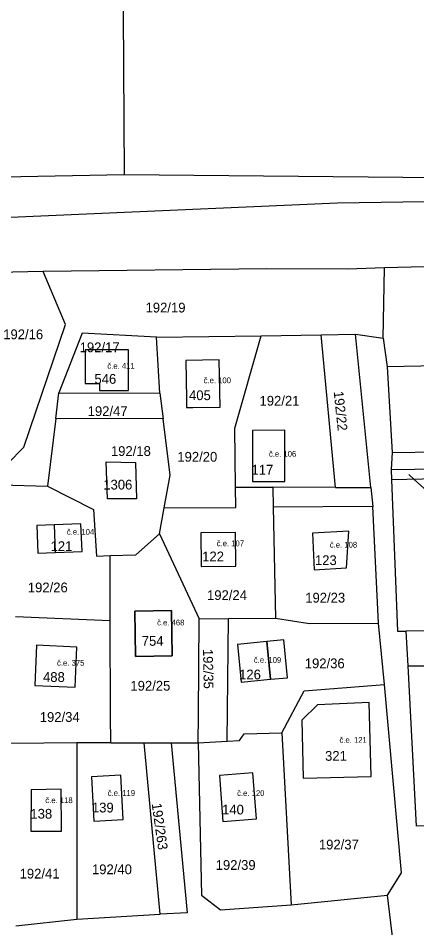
# Model space of a CAD drawing. Extents: x -887272 to -877616, y -1026687 to -1019819.
# Drawn here: x -882463.7 to -882394.3, y -1024170.3 to -1024011.9 of the extents above; entities that cross this region are included whole.
import ezdxf

# ---------------------------------------------------------------- set-up
doc = ezdxf.new("R2010")
doc.units = 0
for name, color, linetype in [('Definiční body', 7, 'Continuous'), ('Hranice parcel', 7, 'Continuous'), ('Parcelní čísla', 7, 'Continuous'), ('Polygon budovy', 7, 'Continuous'), ('Pop  PČ popisy', 7, 'Continuous'), ('Vnitřní kresba', 7, 'Continuous')]:
    doc.layers.add(name, color=color, linetype=linetype)

msp = doc.modelspace()

# ---------------------------------------------------------------- linework, layer by layer
at = {"layer": 'Hranice parcel'}
for p, q in [((-882384.42, -1024039.73), (-882445.26, -1024039.2)), ((-882376.66, -1024054.74), (-882399.93, -1024055.4)), ((-882459.39, -1024055.99), (-882468.38, -1024056.21)), ((-882400.17, -1024067.6), (-882399.93, -1024055.4)), ((-882439.63, -1024067.48), (-882421.39, -1024067.22)), ((-882439.03, -1024077.2), (-882439.63, -1024067.48)), ((-882421.39, -1024067.22), (-882410.99, -1024067.03)), ((-882410.99, -1024067.03), (-882404.99, -1024066.92)), ((-882408.49, -1024093.61), (-882410.99, -1024067.03)), ((-882404.99, -1024066.92), (-882400.17, -1024067.6)), ((-882400.17, -1024067.6), (-882399.46, -1024072.61)), ((-882378.73, -1024072.28), (-882399.46, -1024072.61)), ((-882399.46, -1024072.61), (-882398.59, -1024087.52)), ((-882457.19, -1024081.63), (-882456.65, -1024077.16)), ((-882456.65, -1024077.16), (-882439.03, -1024077.2)), ((-882439.03, -1024077.2), (-882438.47, -1024081.67)), ((-882457.19, -1024081.63), (-882458.6, -1024093.38)), ((-882438.47, -1024081.67), (-882457.19, -1024081.63)), ((-882398.59, -1024087.52), (-882398.79, -1024090.5)), ((-882398.59, -1024087.52), (-882377.91, -1024087.31)), ((-882398.79, -1024090.5), (-882382.57, -1024090.25)), ((-882398.79, -1024090.5), (-882398.72, -1024092.28)), ((-882466.65, -1024093.19), (-882458.6, -1024093.38)), ((-882382.62, -1024092.03), (-882398.72, -1024092.28)), ((-882425.89, -1024093.57), (-882419.37, -1024093.58)), ((-882419.37, -1024093.58), (-882419.3, -1024097.06)), ((-882408.49, -1024093.61), (-882419.37, -1024093.58)), ((-882439.12, -1024101.73), (-882438.28, -1024097.17)), ((-882419.3, -1024097.06), (-882418.9, -1024116.42)), ((-882439.12, -1024101.73), (-882432.22, -1024116.49)), ((-882447.68, -1024116.83), (-882447.72, -1024105.51)), ((-882464.18, -1024116.13), (-882447.68, -1024116.83)), ((-882432.22, -1024116.49), (-882427.09, -1024116.46)), ((-882427.35, -1024137.82), (-882427.09, -1024116.46)), ((-882427.09, -1024116.46), (-882418.9, -1024116.42)), ((-882399.92, -1024127.96), (-882400.99, -1024117.27)), ((-882383.34, -1024118.62), (-882396.14, -1024118.64)), ((-882395.82, -1024124.73), (-882396.14, -1024118.64)), ((-882395.82, -1024124.73), (-882386.09, -1024124.66)), ((-882394.36, -1024152.64), (-882395.82, -1024124.73)), ((-882417.8, -1024136.36), (-882416.18, -1024166.34)), ((-882453.49, -1024138.14), (-882465, -1024138.24)), ((-882453.49, -1024138.14), (-882453.52, -1024168.83)), ((-882447.61, -1024138.14), (-882453.49, -1024138.14)), ((-882447.61, -1024138.14), (-882441.77, -1024138.13)), ((-882438.97, -1024167.97), (-882441.77, -1024138.13)), ((-882441.77, -1024138.13), (-882437.06, -1024138.13)), ((-882437.06, -1024138.13), (-882432.39, -1024138.13)), ((-882432.39, -1024138.13), (-882427.35, -1024137.82)), ((-882385.89, -1024152.42), (-882394.36, -1024152.64)), ((-882416.18, -1024166.34), (-882399.41, -1024164.66)), ((-882398.41, -1024172.81), (-882399.41, -1024164.66)), ((-882464.13, -1024169.99), (-882453.52, -1024168.83)), ((-882453.52, -1024168.83), (-882438.97, -1024167.97))]:
    msp.add_line(p, q, dxfattribs=at)
for points in [[(-882571.48, -1023926.26), (-882445.96, -1023926.09), (-882445.26, -1024039.2)], [(-882445.26, -1024039.2), (-882496.32, -1024040.18), (-882559.82, -1024040.7), (-882602.37, -1024040.09)], [(-882603.02, -1024045.76), (-882539.56, -1024043.76), (-882473.06, -1024046.88), (-882408.1, -1024044.08), (-882339.94, -1024043.02), (-882340.1, -1024040.68)], [(-882465.58, -1024089.52), (-882462.72, -1024086.61), (-882455.48, -1024065.24), (-882459.39, -1024055.99)], [(-882399.93, -1024055.4), (-882406.36, -1024055.62), (-882420.44, -1024055.54), (-882459.39, -1024055.99)], [(-882439.63, -1024067.48), (-882452.56, -1024066.78), (-882456.65, -1024077.16)], [(-882425.89, -1024093.57), (-882425.98, -1024083.3), (-882421.39, -1024067.22)], [(-882408.49, -1024093.61), (-882402.31, -1024093.63), (-882404.99, -1024066.92)], [(-882452.04, -1024069.67), (-882452.03, -1024075.52), (-882449.56, -1024075.52), (-882449.56, -1024076.75), (-882444.53, -1024076.75), (-882444.5, -1024069.65), (-882452.04, -1024069.67)], [(-882434.39, -1024079.72), (-882433.31, -1024079.71), (-882428.57, -1024079.63), (-882428.71, -1024071.42), (-882434.53, -1024071.52), (-882434.42, -1024078.2), (-882434.39, -1024079.72)], [(-882438.28, -1024097.17), (-882437.23, -1024091.5), (-882438.47, -1024081.67)], [(-882417.29, -1024083.68), (-882422.93, -1024083.73), (-882422.91, -1024092.62), (-882417.28, -1024092.58), (-882417.29, -1024083.68)], [(-882448.14, -1024095.6), (-882448.38, -1024089.18), (-882443.3, -1024089.26), (-882443.1, -1024095.6), (-882448.14, -1024095.6)], [(-882398.72, -1024092.28), (-882397.69, -1024118.64), (-882396.14, -1024118.64)], [(-882458.6, -1024093.38), (-882450.61, -1024097.46), (-882450.06, -1024105.58), (-882447.72, -1024105.51)], [(-882438.28, -1024097.17), (-882425.81, -1024097.1), (-882425.89, -1024093.57)], [(-882400.99, -1024117.27), (-882401.99, -1024096.95), (-882419.3, -1024097.06)], [(-882457.28, -1024104.98), (-882452.6, -1024104.8), (-882452.78, -1024099.98), (-882457.45, -1024100.16), (-882460.45, -1024100.28), (-882460.28, -1024105.1), (-882457.28, -1024104.98)], [(-882412.16, -1024108), (-882406.54, -1024107.62), (-882406.16, -1024101.24), (-882412.46, -1024101.62), (-882412.16, -1024108)], [(-882447.72, -1024105.51), (-882443.26, -1024105.38), (-882439.12, -1024101.73)], [(-882425.8, -1024107.33), (-882425.86, -1024101.46), (-882431.91, -1024101.53), (-882431.83, -1024107.39), (-882425.8, -1024107.33)], [(-882436.89, -1024122.96), (-882443.29, -1024123.08), (-882443.39, -1024115.2), (-882437.02, -1024115.09), (-882436.89, -1024122.96)], [(-882447.61, -1024138.14), (-882447.63, -1024133.32), (-882447.68, -1024116.83)], [(-882432.39, -1024138.13), (-882432.35, -1024133.31), (-882432.22, -1024116.49)], [(-882418.9, -1024116.42), (-882412.99, -1024117.3), (-882400.99, -1024117.27)], [(-882425.54, -1024120.96), (-882424.92, -1024127.53), (-882419.79, -1024127.05), (-882416.85, -1024126.78), (-882417.47, -1024120.19), (-882420.41, -1024120.47), (-882425.54, -1024120.96)], [(-882453.8, -1024128.42), (-882453.49, -1024121.43), (-882460.5, -1024121.09), (-882460.79, -1024128.11), (-882453.8, -1024128.42)], [(-882417.8, -1024136.36), (-882413.94, -1024129.03), (-882399.92, -1024127.96)], [(-882399.41, -1024164.66), (-882396.97, -1024160.77), (-882399.92, -1024127.96)], [(-882411.59, -1024131.48), (-882414.33, -1024134.16), (-882414.12, -1024144.27), (-882402.27, -1024143.98), (-882402.59, -1024131.11), (-882411.59, -1024131.48)], [(-882427.35, -1024137.82), (-882425.17, -1024137.68), (-882424.39, -1024136.54), (-882417.8, -1024136.36)], [(-882437.06, -1024138.13), (-882434.29, -1024167.7), (-882438.97, -1024167.97)], [(-882432.39, -1024138.13), (-882431.82, -1024164.63), (-882428.47, -1024167.2), (-882416.18, -1024166.34)], [(-882445.82, -1024143.75), (-882450.96, -1024144.04), (-882450.53, -1024151.78), (-882445.44, -1024151.49), (-882445.82, -1024143.75)], [(-882422.22, -1024151.37), (-882422.84, -1024143.36), (-882428.67, -1024143.82), (-882428.08, -1024151.8), (-882422.22, -1024151.37)], [(-882456.24, -1024146.16), (-882461.48, -1024146.3), (-882461.51, -1024153.52), (-882456.18, -1024153.5), (-882456.24, -1024146.16)]]:
    msp.add_lwpolyline(points, dxfattribs=at)
at = {"layer": 'Polygon budovy'}
for points in [[(-882444.53, -1024076.75), (-882444.5, -1024069.65), (-882452.04, -1024069.67), (-882452.03, -1024075.52), (-882449.56, -1024075.52), (-882449.56, -1024076.75)], [(-882434.53, -1024071.52), (-882434.42, -1024078.2), (-882434.39, -1024079.72), (-882433.31, -1024079.71), (-882428.57, -1024079.63), (-882428.71, -1024071.42)], [(-882422.93, -1024083.73), (-882422.91, -1024092.62), (-882417.28, -1024092.58), (-882417.29, -1024083.68)], [(-882457.45, -1024100.16), (-882457.28, -1024104.98), (-882452.6, -1024104.8), (-882452.78, -1024099.98)], [(-882412.46, -1024101.62), (-882412.16, -1024108), (-882406.54, -1024107.62), (-882406.16, -1024101.24)], [(-882425.86, -1024101.46), (-882431.91, -1024101.53), (-882431.83, -1024107.39), (-882425.8, -1024107.33)], [(-882443.39, -1024115.2), (-882443.29, -1024123.08), (-882436.89, -1024122.96), (-882437.02, -1024115.09)], [(-882460.79, -1024128.11), (-882453.8, -1024128.42), (-882453.49, -1024121.43), (-882460.5, -1024121.09)], [(-882424.92, -1024127.53), (-882419.79, -1024127.05), (-882420.41, -1024120.47), (-882425.54, -1024120.96)], [(-882411.59, -1024131.48), (-882414.33, -1024134.16), (-882414.12, -1024144.27), (-882402.27, -1024143.98), (-882402.59, -1024131.11)], [(-882450.53, -1024151.78), (-882445.44, -1024151.49), (-882445.82, -1024143.75), (-882450.96, -1024144.04)], [(-882428.08, -1024151.8), (-882422.22, -1024151.37), (-882422.84, -1024143.36), (-882428.67, -1024143.82)], [(-882461.48, -1024146.3), (-882461.51, -1024153.52), (-882456.18, -1024153.5), (-882456.24, -1024146.16)]]:
    msp.add_lwpolyline(points, close=True, dxfattribs=at)
at = {"layer": 'Pop  PČ popisy'}
for p, q in [((-882395.72, -1024091.38), (-882394.75, -1024092.24)), ((-882394.75, -1024092.24), (-882392.52, -1024094.25))]:
    msp.add_line(p, q, dxfattribs=at)
at = {"layer": 'Vnitřní kresba'}
for p, q in [((-882402.31, -1024093.63), (-882401.99, -1024096.95)), ((-882457.45, -1024100.16), (-882457.28, -1024104.98)), ((-882420.41, -1024120.47), (-882419.79, -1024127.05))]:
    msp.add_line(p, q, dxfattribs=at)

# ---------------------------------------------------------------- texts
at = {"layer": 'Definiční body'}
for s, p in [('č.e. 411', (-882448.19, -1024072.95)), ('č.e. 100', (-882431.43, -1024075.47)), ('č.e. 106', (-882420.06, -1024088.28)), ('č.e. 104', (-882455.24, -1024101.87)), ('č.e. 107', (-882429.15, -1024103.87)), ('č.e. 108', (-882409.46, -1024104.11)), ('č.e. 468', (-882439.53, -1024117.66)), ('č.e. 109', (-882422.68, -1024124.18)), ('č.e. 375', (-882456.95, -1024124.68)), ('č.e. 121', (-882407.78, -1024138.11)), ('č.e. 119', (-882448.12, -1024147.35)), ('č.e. 120', (-882425.6, -1024147.37)), ('č.e. 118', (-882458.99, -1024148.61))]:
    msp.add_text(s, height=1, dxfattribs=at).set_placement(p)
at = {"layer": 'Parcelní čísla'}
for s, p in [('192/19', (-882441.54, -1024063.15)), ('192/16', (-882466.32, -1024067.81)), ('192/17', (-882453.01, -1024070.07)), ('546', (-882450.44, -1024075.58)), ('405', (-882433.97, -1024078.42)), ('192/21', (-882421.7, -1024079.38)), ('192/47', (-882451.62, -1024081.19)), ('192/18', (-882447.57, -1024088.14)), ('192/20', (-882436.01, -1024089.14)), ('117', (-882423.09, -1024091.39)), ('1306', (-882448.9, -1024093.99)), ('121', (-882458.08, -1024104.71)), ('122', (-882431.68, -1024106.5)), ('123', (-882412.05, -1024107.15)), ('192/26', (-882462.04, -1024111.9)), ('192/24', (-882430.84, -1024113.24)), ('192/23', (-882413.74, -1024113.68)), ('754', (-882442.2, -1024121.21)), ('192/36', (-882413.82, -1024125.12)), ('488', (-882459.39, -1024127.5)), ('126', (-882425.25, -1024127.06)), ('192/25', (-882444.18, -1024129.02)), ('192/34', (-882459.96, -1024134.47)), ('321', (-882410.29, -1024141.24)), ('139', (-882450.88, -1024150.24)), ('138', (-882461.59, -1024151.32)), ('140', (-882428.22, -1024150.59)), ('192/37', (-882411.36, -1024156.68)), ('192/40', (-882450.87, -1024161)), ('192/39', (-882429.33, -1024160.24)), ('192/41', (-882463.47, -1024161.75))]:
    msp.add_text(s, height=1.7, dxfattribs=at).set_placement(p)
for s, rotation, p in [('192/22', 276, (-882408.79, -1024076.94)), ('192/35', 271, (-882431.53, -1024121.77)), ('192/263', 278, (-882440.48, -1024148.72))]:
    msp.add_text(s, height=1.7, rotation=rotation, dxfattribs=at).set_placement(p)

doc.saveas('drawing.dxf')
